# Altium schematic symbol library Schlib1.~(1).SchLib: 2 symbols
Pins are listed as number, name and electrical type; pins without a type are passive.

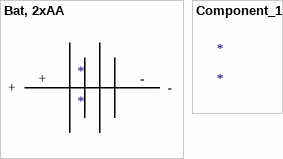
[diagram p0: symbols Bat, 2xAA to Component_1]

## Bat, 2xAA
designator *
pins: +, -

## Component_1
designator *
